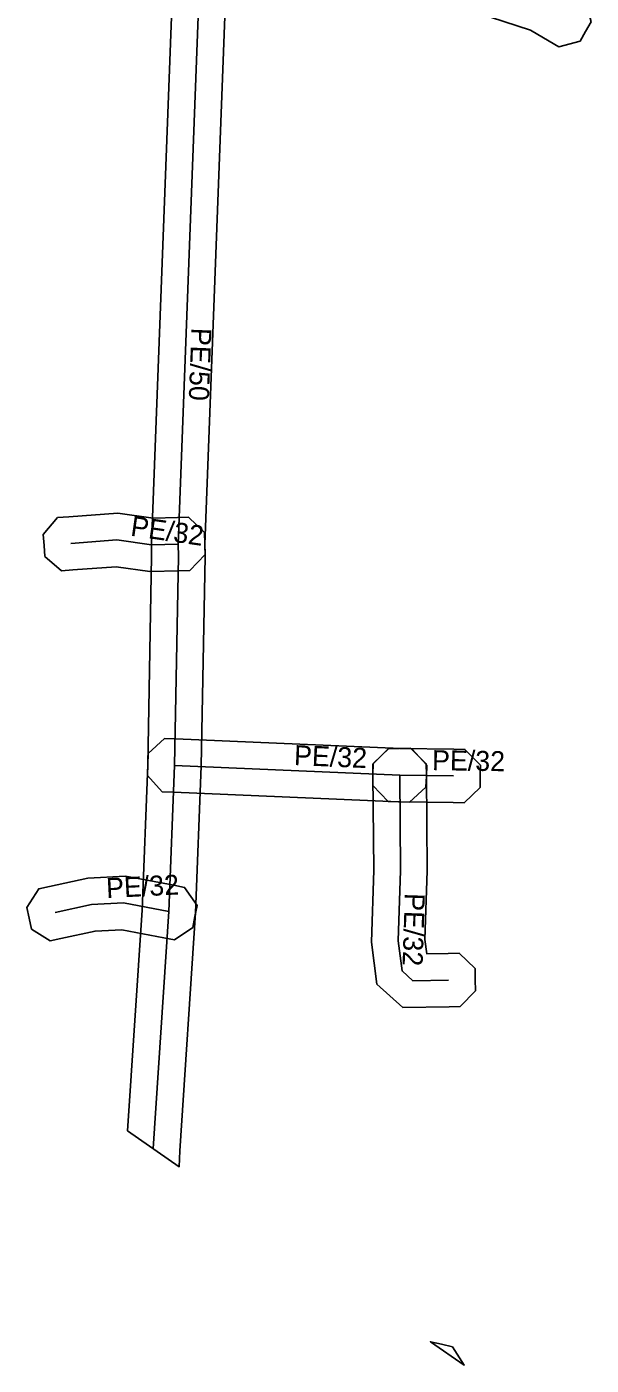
# Model space of a CAD drawing. Extents: x -772893 to -772575, y -1033735 to -1033288.
# Drawn here: x -772893.4 to -772872.3, y -1033636.1 to -1033585.9 of the extents above; entities that cross this region are included whole.
import ezdxf

# ---------------------------------------------------------------- set-up
doc = ezdxf.new("R2010")
doc.units = 0
for name, color, linetype in [('1', 7, 'Continuous'), ('24', 7, 'Continuous'), ('30', 7, 'Continuous')]:
    doc.layers.add(name, color=color, linetype=linetype)

msp = doc.modelspace()

# ---------------------------------------------------------------- linework, layer by layer
at = {"layer": '1'}
for points in [[(-772886.779, -1033579.975), (-772886.385, -1033580.103), (-772873.735, -1033584.229), (-772872.852, -1033584.742), (-772872.494, -1033584.95), (-772872.281, -1033585.751), (-772872.489, -1033586.109), (-772872.697, -1033586.467), (-772873.498, -1033586.68), (-772873.856, -1033586.472), (-772874.557, -1033586.065), (-772887.005, -1033582.005), (-772887.399, -1033581.877), (-772887.774, -1033581.138), (-772887.646, -1033580.744), (-772887.518, -1033580.35)], [(-772887.312, -1033606.315), (-772887.726, -1033606.325), (-772888.806, -1033606.351), (-772890.075, -1033606.169), (-772891.701, -1033606.292), (-772892.114, -1033606.323), (-772892.742, -1033605.783), (-772892.773, -1033605.37), (-772892.804, -1033604.957), (-772892.264, -1033604.329), (-772891.851, -1033604.298), (-772890.009, -1033604.159), (-772888.688, -1033604.347), (-772887.774, -1033604.325), (-772887.36, -1033604.315), (-772886.76, -1033604.887), (-772886.75, -1033605.301), (-772886.74, -1033605.715)], [(-772888.261, -1033612.605), (-772887.847, -1033612.622), (-772879.412, -1033612.977), (-772878.998, -1033612.994), (-772878.438, -1033613.604), (-772878.455, -1033614.018), (-772878.472, -1033614.432), (-772879.082, -1033614.992), (-772879.496, -1033614.975), (-772887.931, -1033614.62), (-772888.345, -1033614.603), (-772888.905, -1033613.993), (-772888.888, -1033613.579), (-772888.871, -1033613.165)], [(-772878.509, -1033620.144), (-772878.439, -1033620.675), (-772877.639, -1033620.661), (-772877.225, -1033620.654), (-772876.629, -1033621.23), (-772876.622, -1033621.644), (-772876.615, -1033622.058), (-772877.191, -1033622.654), (-772877.605, -1033622.661), (-772879.335, -1033622.691), (-772880.305, -1033621.814), (-772880.513, -1033620.244), (-772880.425, -1033617.547), (-772880.454, -1033613.984), (-772880.457, -1033613.57), (-772879.876, -1033612.979), (-772879.462, -1033612.976), (-772879.048, -1033612.973), (-772878.457, -1033613.554), (-772878.454, -1033613.968), (-772878.425, -1033617.571)], [(-772879.852, -1033612.969), (-772879.438, -1033612.976), (-772877.422, -1033613.008), (-772877.008, -1033613.015), (-772876.431, -1033613.61), (-772876.438, -1033614.024), (-772876.445, -1033614.438), (-772877.04, -1033615.015), (-772877.454, -1033615.008), (-772879.47, -1033614.976), (-772879.884, -1033614.969), (-772880.461, -1033614.374), (-772880.454, -1033613.96), (-772880.447, -1033613.546)], [(-772887.883, -1033620.15), (-772888.29, -1033620.073), (-772889.864, -1033619.774), (-772890.864, -1033619.825), (-772892.14, -1033620.105), (-772892.545, -1033620.194), (-772893.242, -1033619.747), (-772893.331, -1033619.342), (-772893.42, -1033618.937), (-772892.973, -1033618.24), (-772892.568, -1033618.151), (-772891.132, -1033617.837), (-772889.726, -1033617.764), (-772887.916, -1033618.109), (-772887.509, -1033618.186), (-772887.044, -1033618.871), (-772887.121, -1033619.278), (-772887.198, -1033619.685)], [(-772877.478, -1033635.4), (-772877.04, -1033636.095), (-772878.306, -1033635.213), (-772877.882, -1033635.309)]]:
    msp.add_lwpolyline(points, close=True, dxfattribs=at)
msp.add_lwpolyline([(-772885.922, -1033583.562), (-772886.75, -1033605.336), (-772886.743, -1033605.788), (-772886.889, -1033613.65), (-772887.104, -1033619.144), (-772887.694, -1033628.064), (-772887.712, -1033628.659), (-772889.649, -1033627.31), (-772889.102, -1033619.038), (-772888.889, -1033613.592), (-772888.743, -1033605.784), (-772888.75, -1033605.314), (-772887.924, -1033583.57)], dxfattribs=at)
at = {"layer": '24'}
for points in [[(-772877.78, -1033569.98), (-772881.579, -1033574.164), (-772885.285, -1033578.498), (-772886.512, -1033580.34), (-772886.695, -1033581.054), (-772886.877, -1033581.768), (-772886.984, -1033582.22), (-772886.923, -1033583.566), (-772887.75, -1033605.325), (-772887.743, -1033605.786), (-772887.889, -1033613.621), (-772888.103, -1033619.091), (-772888.69, -1033627.977)], [(-772887.75, -1033605.325), (-772888.747, -1033605.349), (-772890.042, -1033605.164), (-772891.776, -1033605.295)], [(-772887.889, -1033613.621), (-772879.454, -1033613.976)], [(-772879.454, -1033613.976), (-772879.425, -1033617.559), (-772879.511, -1033620.194), (-772879.362, -1033621.318), (-772878.957, -1033621.684), (-772877.622, -1033621.661)], [(-772879.454, -1033613.976), (-772877.438, -1033614.008)], [(-772888.103, -1033619.091), (-772889.795, -1033618.769), (-772890.998, -1033618.831), (-772892.354, -1033619.128)]]:
    msp.add_lwpolyline(points, dxfattribs=at)

# ---------------------------------------------------------------- texts
at = {"layer": '30'}
for s, rotation, p in [('PE/50', 267.8234, (-772887.249, -1033597.206)), ('PE/32', 351.8699, (-772889.562, -1033605.004)), ('PE/32', 357.59, (-772883.422, -1033613.601)), ('PE/32', 359.0906, (-772878.246, -1033613.792)), ('PE/32', 2.9503, (-772890.43, -1033618.591)), ('PE/32', 268.1307, (-772879.259, -1033618.393))]:
    msp.add_text(s, height=0.75, rotation=rotation, dxfattribs=at).set_placement(p)

doc.saveas('drawing.dxf')
